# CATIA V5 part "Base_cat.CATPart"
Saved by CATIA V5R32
Part number: Base
Bounding box of the stored display mesh (mm): x -24 to 24, y 0 to 90, z 0 to 54
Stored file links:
  D:\PROJECTS\Project 2022\CATIA V5 6R 2022\Resources\Tutorial Files\c14_catia_v5_6r2022_tut\c14tut2\c14tut2.CATParts\Base_cat.CATPart
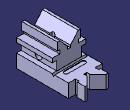
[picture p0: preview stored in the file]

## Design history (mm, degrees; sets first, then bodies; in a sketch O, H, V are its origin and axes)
Body1 (main body)
  Sketch1 on xy-plane, origin (0, 0, 0), H (1, 0, 0), V (0, 1, 0)
    line L1 (-24, 0) -> (24, 0)
    point P2 (24, 0)
    construction line L2 (-23.876, 50.8) -> (23.876, 50.8)
    point P3 (-23.876, 50.8)
    point P4 (23.876, 50.8)
    line L3 (24, 0) -> (24, 74)
    point P5 (24, 74)
    line L4 (24, 74) -> (14, 74)
    point P6 (14, 74)
    line L5 (14, 74) -> (14, 79)
    point P7 (14, 79)
    line L6 (14, 79) -> (16.5, 79)
    point P8 (16.5, 79)
    line L7 (16.5, 79) -> (16.5, 90)
    point P9 (16.5, 90)
    line L8 (16.5, 90) -> (13.5, 90)
    point P10 (13.5, 90)
    line L9 (13.5, 90) -> (2, 78.5)
    point P11 (2, 78.5)
    line L10 (2, 78.5) -> (2, 74)
    point P12 (2, 74)
    line L11 (2, 74) -> (0, 74)
    point P13 (0, 74)
    point P14 (0, 74)
    point P15 (-2, 74)
    line L12 (-2, 74) -> (0, 74)
    point P16 (-2, 78.5)
    line L13 (-2, 78.5) -> (-2, 74)
    point P17 (-13.5, 90)
    line L14 (-13.5, 90) -> (-2, 78.5)
    point P18 (-16.5, 90)
    line L15 (-16.5, 90) -> (-13.5, 90)
    point P19 (-16.5, 79)
    line L16 (-16.5, 79) -> (-16.5, 90)
    point P20 (-14, 79)
    line L17 (-14, 79) -> (-16.5, 79)
    point P21 (-14, 74)
    line L18 (-14, 74) -> (-14, 79)
    point P22 (-24, 74)
    line L19 (-24, 74) -> (-14, 74)
    point P23 (-23.876, 50.8)
    point P24 (23.876, 50.8)
    construction line L20 (23.876, 50.8) -> (-23.876, 50.8)
    point P25 (-24, 0)
    line L21 (-24, 0) -> (-24, 74)
    distance P2 V = 24
    distance L13 L10 = 4
    distance L16 L7 = 33
    distance L5 L3 = 10
    length L18 = 5
    angle L14 L9 = 90
    distance L4 L8 = 16
    distance P17 P10 = 27
    distance L1 L8 = 90
    length L1 = 48
    horizontal: L1 H, L2 H, L4 H, L6 H, L8 H, L11 H
    coincidence: H L1, P13 V, P13 P14, L12 L4
    vertical: L3 V, L5 V, L7 V, L10 V
    symmetry: P13 P14 V, P12 P15 V, L11 L12 V, P11 P16 V, L10 L13 V, P10 P17 V, L9 L14 V, P9 P18 V, L8 L15 V, P8 P19 V, L7 L16 V, P7 P20 V, L6 L17 V, P6 P21 V, L5 L18 V, P5 P22 V, L4 L19 V, P4 P23 V, P3 P24 V, L2 L20 V, P2 P25 V, L3 L21 V
  Pad1: profile Sketch1, direction (0, 0, 1), length 19
  Sketch2 on face of Pad1, origin (0, 0, 0), H (1, 0, 0), V (0, 0, 1)
    line L1 (17.5, 19) -> (17.5, 32)
    point P1 (17.5, 19)
    point P2 (17.5, 32)
    line L2 (17.5, 32) -> (24, 32)
    point P3 (24, 32)
    line L3 (24, 32) -> (24, 38)
    point P4 (24, 38)
    line L4 (24, 38) -> (13.5, 38)
    point P5 (13.5, 38)
    line L5 (13.5, 38) -> (13.5, 43)
    point P6 (13.5, 43)
    line L6 (13.5, 43) -> (16.5, 43)
    point P7 (16.5, 43)
    line L7 (16.5, 43) -> (16.5, 54)
    point P8 (16.5, 54)
    reference projected line E1 (24, 19) -> (-24, 19) from edge of Pad1
    reference projected line E2 (24, 0) -> (24, 19) from edge of Pad1
    line L8 (16.5, 54) -> (12.9083, 54)
    point P9 (12.9083, 54)
    point P10 (2, 41)
    line L9 (2, 41) -> (2, 38)
    point P11 (2, 38)
    line L10 (2, 38) -> (0, 38)
    point P12 (0, 38)
    line L11 (2, 41) -> (12.9083, 54)
    point P13 (-12.9083, 54)
    point P14 (-2, 41)
    line L12 (-2, 41) -> (-12.9083, 54)
    point P15 (0, 38)
    point P16 (-2, 38)
    line L13 (-2, 38) -> (0, 38)
    line L14 (-2, 41) -> (-2, 38)
    point P17 (-16.5, 54)
    line L15 (-16.5, 54) -> (-12.9083, 54)
    point P18 (-16.5, 43)
    line L16 (-16.5, 43) -> (-16.5, 54)
    point P19 (-13.5, 43)
    line L17 (-13.5, 43) -> (-16.5, 43)
    point P20 (-13.5, 38)
    line L18 (-13.5, 38) -> (-13.5, 43)
    point P21 (-24, 38)
    line L19 (-24, 38) -> (-13.5, 38)
    point P22 (-24, 32)
    line L20 (-24, 32) -> (-24, 38)
    point P23 (-17.5, 32)
    line L21 (-17.5, 32) -> (-24, 32)
    point P24 (-17.5, 19)
    line L22 (-17.5, 19) -> (-17.5, 32)
    line L23 (-17.5, 19) -> (17.5, 19)
    distance L2 H = 32
    distance L4 H = 38
    distance L6 H = 43
    distance L8 H = 54
    distance L9 V = 2
    length L9 = 3
    distance L22 L1 = 35
    distance L7 L16 = 33
    angle L12 L11 = 80
    distance L18 L5 = 27
    vertical: L1 V, L3 V, L5 V, L7 V, L9 V
    horizontal: L2 H, L4 H, L6 H, L8 H, L10 H, L23 H
    coincidence: P1 E1, L3 E2, P11 L4, P12 V, P12 P15
    symmetry: P9 P13 V, P10 P14 V, L11 L12 V, P12 P15 V, P11 P16 V, L10 L13 V, L9 L14 V, P8 P17 V, L8 L15 V, P7 P18 V, L7 L16 V, P6 P19 V, L6 L17 V, P5 P20 V, L5 L18 V, P4 P21 V, L4 L19 V, P3 P22 V, L3 L20 V, P2 P23 V, L2 L21 V, P1 P24 V, L1 L22 V
  Pad2: profile Sketch2, direction (0, 1, 0), length 50.8
  Sketch3 on face of Pad1, origin (4.0235, 27.8102, 0), H (1, 0, 0), V (0, -1, 0)
    point P1 (-4.0235, 2.8102)
    reference intersected line E1 through (-4.0235, 0) direction (0, 1) from yz-plane
    reference projected line E2 (-6.0235, 27.8102) -> (-16.9318, 27.8102) from edge [face of Pad2 from Sketch2.L12 | start face of Pad2]
    distance P1 E2 = 25
    coincidence: E1 P1
  Hole1: placed by Sketch3, at (0, 25, 0) direction (0, 0, 1), diameter 8, depth 54.102
  Sketch4 on face of Pad2, origin (17.5, 12.3932, 23.5222), H (0, 1, 0), V (0, 0, 1)
    point P1 (12.6068, 1.4778)
    reference projected line E1 (-12.3932, 8.4778) -> (-12.3932, -4.5222) from edge of Pad2
    reference projected line E2 (-12.3932, -23.5222) -> (61.6068, -23.5222) from edge of Pad1
    distance E1 P1 = 25
    distance E2 P1 = 25
  Hole2: placed by Sketch4, at (17.5, 25, 25) direction (-1, 0, 0), diameter 10, depth 54.102
  Sketch5 on face of Pad1, origin (0, 0, 19), H (1, 0, 0), V (0, 1, 0)
    construction line L1 (-24, 59) -> (24, 59)
    point P1 (-24, 59)
    point P2 (24, 59)
    construction line L2 (-12.5, 59) -> (12.5, 59)
    point P3 (-12.5, 59)
    point P4 (12.5, 59)
    line L3 (-12.5, 62) -> (12.5, 62)
    line L4 (12.5, 56) -> (-12.5, 56)
    arc A1 centre (12.5, 59) radius 3 from (12.5, 62) to (12.5, 56) cw
    arc A2 centre (-12.5, 59) radius 3 from (-12.5, 56) to (-12.5, 62) cw
    reference projected line E1 (24, 74) -> (24, 0) from edge of Pad1
    reference projected line E2 (-24, 74) -> (-24, 0) from edge of Pad1
    reference projected line E3 (24, 74) -> (14, 74) from edge [face of Pad1 from Sketch1.L4 | end face of Pad1]
    radius A1 = 3
    distance L2 E3 = 15
    length L2 = 25
    distance V P4 = 12.5
    horizontal: L1 H, L2 H
    coincidence: P3 L1, P2 E1, P1 E2
    tangency: A1 L3, A2 L3, A1 L4, A2 L4
    parallelism: L2 L3
  Pocket1: profile Sketch5, direction (0, 0, -1), length 1
  Sketch6 on face of Pad1, origin (24, 0, 0), H (0, 1, 0), V (0, 0, 1)
    point P1 (50.8, 19)
    line L1 (50.8, 19) -> (52.5321, 16)
    point P2 (52.5321, 16)
    line L2 (52.5321, 16) -> (54.2641, 19)
    line L3 (54.2641, 19) -> (50.8, 19)
    reference projected line E1 (74, 19) -> (0, 19) from edge of Pad1
    construction line L4 (52.5321, 16) -> (52.5321, 29.45)
    reference projected line E2 (50.8, 19) -> (50.8, 32) from edge [end face of Pad2 | face of Pad2 from Sketch2.L1]
    angle L1 L2 = 60
    distance P2 L3 = 3
    angle L4 L2 = 30
    horizontal: L3 H
    coincidence: L3 E1, P1 E2
    vertical: L4 V
  Pocket2: profile Sketch6, direction (-1, 0, 0), through (limit type 6)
